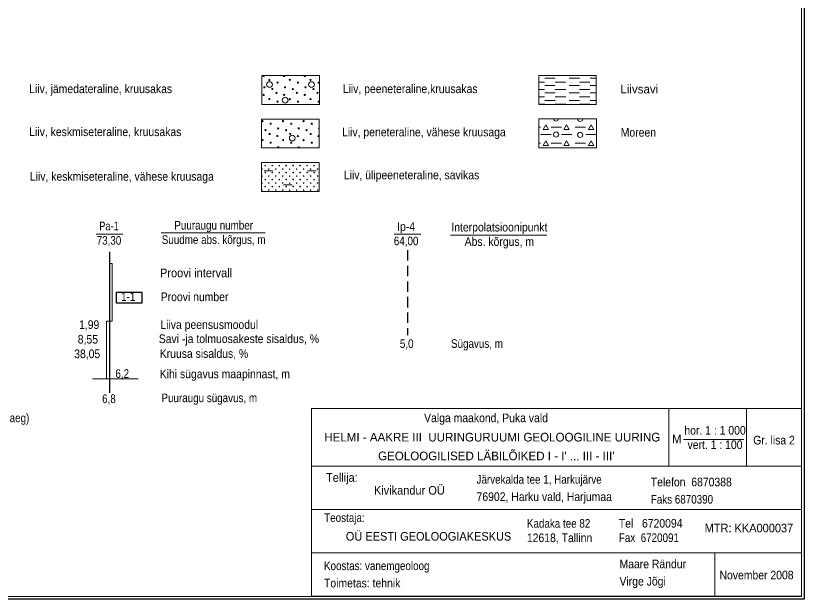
# Model space of a CAD drawing. Extents: x 640104 to 640970, y 6442278 to 6442689.
# Drawn here: x 640696.8 to 640970.3, y 6442282.5 to 6442484.9 of the extents above; entities that cross this region are included whole.
import ezdxf
from ezdxf.enums import TextEntityAlignment as Align

# ---------------------------------------------------------------- set-up
doc = ezdxf.new("R2010")
doc.units = 0
doc.header["$LTSCALE"] = 1.2
doc.linetypes.add('MEDIUM_DASHED', pattern=[4.5, 3, -1.5])
doc.layers.add('50', color=7, linetype='Continuous', lineweight=13)

msp = doc.modelspace()

# ---------------------------------------------------------------- hatches: boundary and pattern name
at = {"layer": '50'}
for points in [[(640784.939, 6442462.605, 1), (640784.519, 6442462.605, 1)], [(640787.767, 6442461.697, 1), (640787.347, 6442461.697, 1)], [(640792.072, 6442462.605, 1), (640791.652, 6442462.605, 1)], [(640794.9, 6442461.697, 1), (640794.48, 6442461.697, 1)], [(640799.205, 6442462.605, 1), (640798.785, 6442462.605, 1)], [(640802.033, 6442461.697, 1), (640801.613, 6442461.697, 1)], [(640783.236, 6442460.072, 1), (640782.816, 6442460.072, 1)], [(640785.983, 6442459.466, 1), (640785.563, 6442459.466, 1)], [(640787.402, 6442458.144, 1), (640786.982, 6442458.144, 1)], [(640790.369, 6442460.072, 1), (640789.949, 6442460.072, 1)], [(640793.116, 6442459.466, 1), (640792.696, 6442459.466, 1)], [(640794.535, 6442458.144, 1), (640794.115, 6442458.144, 1)], [(640797.502, 6442460.072, 1), (640797.082, 6442460.072, 1)], [(640800.249, 6442459.466, 1), (640799.829, 6442459.466, 1)], [(640801.668, 6442458.144, 1), (640801.248, 6442458.144, 1)], [(640782.962, 6442457.428, 1), (640782.542, 6442457.428, 1)], [(640784.939, 6442456.009, 1), (640784.519, 6442456.009, 1)], [(640787.767, 6442455.101, 1), (640787.347, 6442455.101, 1)], [(640790.095, 6442457.428, 1), (640789.675, 6442457.428, 1)], [(640792.072, 6442456.009, 1), (640791.652, 6442456.009, 1)], [(640794.9, 6442455.101, 1), (640794.48, 6442455.101, 1)], [(640797.228, 6442457.428, 1), (640796.808, 6442457.428, 1)], [(640799.205, 6442456.009, 1), (640798.785, 6442456.009, 1)], [(640802.033, 6442455.101, 1), (640801.613, 6442455.101, 1)], [(640782.559, 6442448.354, 1), (640782.139, 6442448.354, 1)], [(640785.386, 6442447.446, 1), (640784.966, 6442447.446, 1)], [(640789.692, 6442448.354, 1), (640789.272, 6442448.354, 1)], [(640792.519, 6442447.446, 1), (640792.099, 6442447.446, 1)], [(640796.825, 6442448.354, 1), (640796.405, 6442448.354, 1)], [(640799.652, 6442447.446, 1), (640799.232, 6442447.446, 1)], [(640783.603, 6442445.215, 1), (640783.183, 6442445.215, 1)], [(640787.989, 6442445.82, 1), (640787.569, 6442445.82, 1)], [(640790.736, 6442445.215, 1), (640790.316, 6442445.215, 1)], [(640795.122, 6442445.82, 1), (640794.702, 6442445.82, 1)], [(640797.869, 6442445.215, 1), (640797.449, 6442445.215, 1)], [(640782.559, 6442441.758, 1), (640782.139, 6442441.758, 1)], [(640785.022, 6442443.893, 1), (640784.602, 6442443.893, 1)], [(640787.714, 6442443.177, 1), (640787.294, 6442443.177, 1)], [(640789.692, 6442441.758, 1), (640789.272, 6442441.758, 1)], [(640792.155, 6442443.893, 1), (640791.735, 6442443.893, 1)], [(640794.847, 6442443.177, 1), (640794.427, 6442443.177, 1)], [(640796.825, 6442441.758, 1), (640796.405, 6442441.758, 1)], [(640799.288, 6442443.893, 1), (640798.868, 6442443.893, 1)], [(640801.98, 6442443.177, 1), (640801.56, 6442443.177, 1)], [(640785.386, 6442440.85, 1), (640784.966, 6442440.85, 1)], [(640792.519, 6442440.85, 1), (640792.099, 6442440.85, 1)], [(640799.652, 6442440.85, 1), (640799.232, 6442440.85, 1)], [(640783.399, 6442432.982, 1), (640783.25, 6442432.833, 1)], [(640783.399, 6442430.563, 1), (640783.25, 6442430.415, 1)], [(640784.608, 6442431.773, 1), (640784.459, 6442431.624, 1)], [(640785.817, 6442432.982, 1), (640785.669, 6442432.833, 1)], [(640785.817, 6442430.563, 1), (640785.669, 6442430.415, 1)], [(640787.026, 6442431.773, 1), (640786.878, 6442431.624, 1)], [(640788.235, 6442432.982, 1), (640788.087, 6442432.833, 1)], [(640788.235, 6442430.563, 1), (640788.087, 6442430.415, 1)], [(640789.445, 6442431.773, 1), (640789.296, 6442431.624, 1)], [(640790.654, 6442432.982, 1), (640790.505, 6442432.833, 1)], [(640790.654, 6442430.563, 1), (640790.505, 6442430.415, 1)], [(640791.863, 6442431.773, 1), (640791.714, 6442431.624, 1)], [(640793.072, 6442432.982, 1), (640792.924, 6442432.833, 1)], [(640793.072, 6442430.563, 1), (640792.924, 6442430.415, 1)], [(640794.281, 6442431.773, 1), (640794.133, 6442431.624, 1)], [(640795.49, 6442432.982, 1), (640795.342, 6442432.833, 1)], [(640795.49, 6442430.563, 1), (640795.342, 6442430.415, 1)], [(640796.699, 6442431.773, 1), (640796.551, 6442431.624, 1)], [(640797.909, 6442432.982, 1), (640797.76, 6442432.833, 1)], [(640797.909, 6442430.563, 1), (640797.76, 6442430.415, 1)], [(640799.118, 6442431.773, 1), (640798.969, 6442431.624, 1)], [(640800.327, 6442432.982, 1), (640800.178, 6442432.833, 1)], [(640800.327, 6442430.563, 1), (640800.178, 6442430.415, 1)], [(640801.536, 6442431.773, 1), (640801.388, 6442431.624, 1)], [(640783.399, 6442428.145, 1), (640783.25, 6442427.997, 1)], [(640784.608, 6442429.354, 1), (640784.459, 6442429.206, 1)], [(640785.817, 6442428.145, 1), (640785.669, 6442427.997, 1)], [(640787.026, 6442429.354, 1), (640786.878, 6442429.206, 1)], [(640788.235, 6442428.145, 1), (640788.087, 6442427.997, 1)], [(640789.445, 6442429.354, 1), (640789.296, 6442429.206, 1)], [(640790.654, 6442428.145, 1), (640790.505, 6442427.997, 1)], [(640791.863, 6442429.354, 1), (640791.714, 6442429.206, 1)], [(640793.072, 6442428.145, 1), (640792.924, 6442427.997, 1)], [(640794.281, 6442429.354, 1), (640794.133, 6442429.206, 1)], [(640795.49, 6442428.145, 1), (640795.342, 6442427.997, 1)], [(640796.699, 6442429.354, 1), (640796.551, 6442429.206, 1)], [(640797.909, 6442428.145, 1), (640797.76, 6442427.997, 1)], [(640799.118, 6442429.354, 1), (640798.969, 6442429.206, 1)], [(640800.327, 6442428.145, 1), (640800.178, 6442427.997, 1)], [(640801.536, 6442429.354, 1), (640801.388, 6442429.206, 1)], [(640783.399, 6442425.727, 1), (640783.25, 6442425.578, 1)], [(640784.608, 6442426.936, 1), (640784.459, 6442426.787, 1)], [(640785.817, 6442425.727, 1), (640785.669, 6442425.578, 1)], [(640787.026, 6442426.936, 1), (640786.878, 6442426.787, 1)], [(640788.235, 6442425.727, 1), (640788.087, 6442425.578, 1)], [(640789.445, 6442426.936, 1), (640789.296, 6442426.787, 1)], [(640790.654, 6442425.727, 1), (640790.505, 6442425.578, 1)], [(640791.863, 6442426.936, 1), (640791.714, 6442426.787, 1)], [(640793.072, 6442425.727, 1), (640792.924, 6442425.578, 1)], [(640794.281, 6442426.936, 1), (640794.133, 6442426.787, 1)], [(640795.49, 6442425.727, 1), (640795.342, 6442425.578, 1)], [(640796.699, 6442426.936, 1), (640796.551, 6442426.787, 1)], [(640797.909, 6442425.727, 1), (640797.76, 6442425.578, 1)], [(640799.118, 6442426.936, 1), (640798.969, 6442426.787, 1)], [(640800.327, 6442425.727, 1), (640800.178, 6442425.578, 1)], [(640801.536, 6442426.936, 1), (640801.388, 6442426.787, 1)], [(640784.608, 6442424.518, 1), (640784.459, 6442424.369, 1)], [(640787.026, 6442424.518, 1), (640786.878, 6442424.369, 1)], [(640789.445, 6442424.518, 1), (640789.296, 6442424.369, 1)], [(640791.863, 6442424.518, 1), (640791.714, 6442424.369, 1)], [(640794.281, 6442424.518, 1), (640794.133, 6442424.369, 1)], [(640796.699, 6442424.518, 1), (640796.551, 6442424.369, 1)], [(640799.118, 6442424.518, 1), (640798.969, 6442424.369, 1)], [(640801.536, 6442424.518, 1), (640801.388, 6442424.369, 1)]]:
    msp.add_hatch(color=256, dxfattribs=at).paths.add_polyline_path(points)

# ---------------------------------------------------------------- linework, layer by layer
for p, q in [((640880.24, 6442461.89), (640878.17, 6442461.89)), ((640883.94, 6442463.25), (640880.34, 6442463.25)), ((640883.94, 6442460.68), (640880.34, 6442460.68)), ((640887.54, 6442461.88), (640883.94, 6442461.88)), ((640892.34, 6442463.25), (640888.74, 6442463.25)), ((640892.34, 6442460.68), (640888.74, 6442460.68)), ((640895.95, 6442461.89), (640892.35, 6442461.89)), ((640898.17, 6442463.25), (640896.05, 6442463.25)), ((640898.17, 6442460.68), (640896.05, 6442460.68)), ((640880.24, 6442459.32), (640878.17, 6442459.32)), ((640883.94, 6442458.11), (640880.34, 6442458.11)), ((640887.54, 6442459.31), (640883.94, 6442459.31)), ((640892.34, 6442458.11), (640888.74, 6442458.11)), ((640895.95, 6442459.32), (640892.35, 6442459.32)), ((640898.17, 6442458.11), (640896.05, 6442458.11)), ((640880.24, 6442456.75), (640878.17, 6442456.75)), ((640883.94, 6442455.54), (640880.34, 6442455.54)), ((640887.54, 6442456.74), (640883.94, 6442456.74)), ((640892.34, 6442455.54), (640888.74, 6442455.54)), ((640895.95, 6442456.75), (640892.35, 6442456.75)), ((640898.17, 6442455.54), (640896.05, 6442455.54)), ((640880.24, 6442454.18), (640878.17, 6442454.18)), ((640887.54, 6442454.17), (640883.94, 6442454.17)), ((640895.95, 6442454.18), (640892.35, 6442454.18)), ((640878.76, 6442446.3), (640878.23, 6442446.3)), ((640886.06, 6442446.29), (640882.46, 6442446.29)), ((640894.46, 6442446.3), (640890.86, 6442446.3)), ((640898.23, 6442446.29), (640898.15, 6442446.29)), ((640882.46, 6442443.74), (640878.86, 6442443.74)), ((640889.66, 6442443.73), (640886.06, 6442443.73)), ((640898.15, 6442443.74), (640894.55, 6442443.74)), ((640878.76, 6442440.74), (640878.23, 6442440.74)), ((640886.06, 6442440.74), (640882.46, 6442440.74)), ((640894.46, 6442440.74), (640890.86, 6442440.74)), ((640898.23, 6442440.74), (640898.15, 6442440.74)), ((640782.89, 6442431.05), (640785.89, 6442431.05)), ((640798.02, 6442431.05), (640801.02, 6442431.05)), ((640789.65, 6442426.19), (640792.65, 6442426.19)), ((640724.64, 6442409.13), (640733.86, 6442409.13)), ((640747.19, 6442409.65), (640783.26, 6442409.65)), ((640828.06, 6442409.13), (640837.28, 6442409.13)), ((640847.59, 6442408.76), (640880.99, 6442408.76)), ((640723.43, 6442359.01), (640739.23, 6442359.01)), ((640923.29, 6442328.63), (640923.29, 6442348.63)), ((640950.3, 6442328.63), (640950.3, 6442348.63)), ((640928.43, 6442337.96), (640949.3, 6442337.96)), ((640799.3, 6442328.63), (640969.3, 6442328.63)), ((640814.82, 6442325.4), (640814.8, 6442325.38)), ((640799.3, 6442313.63), (640969.3, 6442313.63)), ((640799.3, 6442298.63), (640969.3, 6442298.63)), ((640939.3, 6442283.63), (640939.3, 6442298.63))]:
    msp.add_line(p, q, dxfattribs=at)
at = {"layer": '50', "linetype": 'MEDIUM_DASHED', "lineweight": 25}
msp.add_line((640832.65, 6442403.55), (640832.65, 6442374.14), dxfattribs=at)
at = {"layer": '50', "lineweight": 25}
msp.add_line((640729.23, 6442403.02), (640729.23, 6442354.12), dxfattribs=at)
for points in [[(640103.56, 6442688.99), (640970.3, 6442688.99), (640970.3, 6442282.54), (640103.56, 6442282.54)], [(640731.74, 6442389.04), (640740.45, 6442389.04), (640740.45, 6442385.24), (640731.74, 6442385.24)]]:
    msp.add_lwpolyline(points, close=True, dxfattribs=at)
at = {"layer": '50'}
for points in [[(640104.56, 6442687.99), (640969.3, 6442687.99), (640969.3, 6442283.54), (640104.56, 6442283.54)], [(640782.11, 6442464.13), (640802.11, 6442464.13), (640802.11, 6442454.13), (640782.11, 6442454.13)], [(640878.17, 6442464.13), (640898.17, 6442464.13), (640898.17, 6442454.13), (640878.17, 6442454.13)], [(640782.04, 6442449.06), (640802.04, 6442449.06), (640802.04, 6442439.06), (640782.04, 6442439.06)], [(640878.23, 6442449.1), (640898.23, 6442449.1), (640898.23, 6442439.1), (640878.23, 6442439.1)], [(640782.03, 6442433.97), (640802.03, 6442433.97), (640802.03, 6442423.97), (640782.03, 6442423.97)], [(640730.23, 6442379.01), (640730.23, 6442399.01), (640729.23, 6442399.01), (640729.23, 6442379.01)], [(640728.23, 6442379.01), (640728.23, 6442359.01), (640729.23, 6442359.01), (640729.23, 6442379.01)], [(640969.3, 6442348.63), (640799.3, 6442348.63), (640799.3, 6442283.63), (640969.3, 6442283.63)]]:
    msp.add_lwpolyline(points, close=True, dxfattribs=at)
for points in [[(640879.7, 6442445.46), (640879.7, 6442445.49), (640880.65, 6442447.02), (640881.58, 6442445.48), (640879.78, 6442445.49)], [(640886.92, 6442445.46), (640886.92, 6442445.49), (640887.87, 6442447.02), (640888.8, 6442445.48), (640887, 6442445.49)], [(640895.39, 6442445.46), (640895.4, 6442445.49), (640896.34, 6442447.02), (640897.27, 6442445.48), (640895.47, 6442445.49)], [(640879.7, 6442439.91), (640879.7, 6442439.93), (640880.65, 6442441.46), (640881.58, 6442439.92), (640879.78, 6442439.93)], [(640886.92, 6442439.91), (640886.92, 6442439.93), (640887.87, 6442441.46), (640888.8, 6442439.92), (640887, 6442439.93)], [(640895.39, 6442439.91), (640895.4, 6442439.93), (640896.34, 6442441.46), (640897.27, 6442439.92), (640895.47, 6442439.93)]]:
    msp.add_lwpolyline(points, dxfattribs=at)
for centre, radius in [((640784.793, 6442461.022), 1), ((640784.729, 6442462.605), 0.21), ((640787.557, 6442461.697), 0.21), ((640791.862, 6442462.605), 0.21), ((640794.69, 6442461.697), 0.21), ((640799.353, 6442461.022), 1), ((640798.995, 6442462.605), 0.21), ((640801.823, 6442461.697), 0.21), ((640783.026, 6442460.072), 0.21), ((640785.773, 6442459.466), 0.21), ((640787.192, 6442458.144), 0.21), ((640790.159, 6442460.072), 0.21), ((640792.906, 6442459.466), 0.21), ((640794.325, 6442458.144), 0.21), ((640797.292, 6442460.072), 0.21), ((640800.039, 6442459.466), 0.21), ((640801.458, 6442458.144), 0.21), ((640782.752, 6442457.428), 0.21), ((640784.729, 6442456.009), 0.21), ((640787.557, 6442455.101), 0.21), ((640790.217, 6442455.598), 1), ((640789.885, 6442457.428), 0.21), ((640791.862, 6442456.009), 0.21), ((640794.69, 6442455.101), 0.21), ((640797.018, 6442457.428), 0.21), ((640798.995, 6442456.009), 0.21), ((640801.823, 6442455.101), 0.21), ((640782.349, 6442448.354), 0.21), ((640785.176, 6442447.446), 0.21), ((640789.482, 6442448.354), 0.21), ((640792.309, 6442447.446), 0.21), ((640796.615, 6442448.354), 0.21), ((640799.442, 6442447.446), 0.21), ((640783.393, 6442445.215), 0.21), ((640787.779, 6442445.82), 0.21), ((640790.526, 6442445.215), 0.21), ((640794.912, 6442445.82), 0.21), ((640797.659, 6442445.215), 0.21), ((640884.207, 6442443.687), 0.9), ((640892.589, 6442443.564), 0.9), ((640782.349, 6442441.758), 0.21), ((640784.812, 6442443.893), 0.21), ((640787.504, 6442443.177), 0.21), ((640789.482, 6442441.758), 0.21), ((640792.691, 6442442.465), 1), ((640791.945, 6442443.893), 0.21), ((640794.637, 6442443.177), 0.21), ((640796.615, 6442441.758), 0.21), ((640799.078, 6442443.893), 0.21), ((640801.77, 6442443.177), 0.21), ((640785.176, 6442440.85), 0.21), ((640792.309, 6442440.85), 0.21), ((640799.442, 6442440.85), 0.21), ((640783.325, 6442432.907), 0.105), ((640783.325, 6442430.489), 0.105), ((640784.534, 6442431.698), 0.105), ((640785.743, 6442432.907), 0.105), ((640785.743, 6442430.489), 0.105), ((640786.952, 6442431.698), 0.105), ((640788.161, 6442432.907), 0.105), ((640788.161, 6442430.489), 0.105), ((640789.37, 6442431.698), 0.105), ((640790.579, 6442432.907), 0.105), ((640790.579, 6442430.489), 0.105), ((640791.789, 6442431.698), 0.105), ((640792.998, 6442432.907), 0.105), ((640792.998, 6442430.489), 0.105), ((640794.207, 6442431.698), 0.105), ((640795.416, 6442432.907), 0.105), ((640795.416, 6442430.489), 0.105), ((640796.625, 6442431.698), 0.105), ((640797.834, 6442432.907), 0.105), ((640797.834, 6442430.489), 0.105), ((640799.044, 6442431.698), 0.105), ((640800.253, 6442432.907), 0.105), ((640800.253, 6442430.489), 0.105), ((640801.462, 6442431.698), 0.105), ((640783.325, 6442428.071), 0.105), ((640784.534, 6442429.28), 0.105), ((640785.743, 6442428.071), 0.105), ((640786.952, 6442429.28), 0.105), ((640788.161, 6442428.071), 0.105), ((640789.37, 6442429.28), 0.105), ((640790.579, 6442428.071), 0.105), ((640791.789, 6442429.28), 0.105), ((640792.998, 6442428.071), 0.105), ((640794.207, 6442429.28), 0.105), ((640795.416, 6442428.071), 0.105), ((640796.625, 6442429.28), 0.105), ((640797.834, 6442428.071), 0.105), ((640799.044, 6442429.28), 0.105), ((640800.253, 6442428.071), 0.105), ((640801.462, 6442429.28), 0.105), ((640783.325, 6442425.653), 0.105), ((640784.534, 6442426.862), 0.105), ((640785.743, 6442425.653), 0.105), ((640786.952, 6442426.862), 0.105), ((640788.161, 6442425.653), 0.105), ((640789.37, 6442426.862), 0.105), ((640790.579, 6442425.653), 0.105), ((640791.789, 6442426.862), 0.105), ((640792.998, 6442425.653), 0.105), ((640794.207, 6442426.862), 0.105), ((640795.416, 6442425.653), 0.105), ((640796.625, 6442426.862), 0.105), ((640797.834, 6442425.653), 0.105), ((640799.044, 6442426.862), 0.105), ((640800.253, 6442425.653), 0.105), ((640801.462, 6442426.862), 0.105), ((640784.534, 6442424.443), 0.105), ((640786.952, 6442424.443), 0.105), ((640789.37, 6442424.443), 0.105), ((640791.789, 6442424.443), 0.105), ((640794.207, 6442424.443), 0.105), ((640796.625, 6442424.443), 0.105), ((640799.044, 6442424.443), 0.105), ((640801.462, 6442424.443), 0.105)]:
    msp.add_circle(centre, radius, dxfattribs=at)
for centre, radius, start, end in [((640782.752, 6442464.024), 0.21, 150.74597, 29.25403), ((640789.885, 6442464.024), 0.21, 150.74597, 29.25403), ((640797.018, 6442464.024), 0.21, 150.74597, 29.25403), ((640884.207, 6442449.241), 0.9, 188.96929, 351.03071), ((640892.589, 6442449.119), 0.9, 181.15583, 358.84417), ((640802.045, 6442445.82), 0.21, 91.76464, 268.23536), ((640787.779, 6442439.224), 0.21, 306.48162, 233.51838), ((640794.912, 6442439.224), 0.21, 306.48162, 233.51838), ((640802.045, 6442439.224), 0.21, 91.76464, 233.51838), ((640782.115, 6442431.698), 0.105, 212.33453, 147.66547), ((640782.115, 6442429.28), 0.105, 212.33453, 147.66547), ((640782.115, 6442426.862), 0.105, 212.33453, 147.66547), ((640782.115, 6442424.443), 0.105, 212.33453, 147.66547)]:
    msp.add_arc(centre, radius, start, end, dxfattribs=at)

# ---------------------------------------------------------------- texts
for s, width, p in [('Liiv, jämedateraline, kruusakas', 0.9, (640726.205, 6442458.05)), ('Liiv, peeneteraline,kruusakas', 0.9, (640833.59, 6442458.06)), ('Liiv, keskmiseteraline, kruusakas', 0.9, (640727.835, 6442443.15)), ('Liiv, peneteraline, vähese kruusaga', 0.9, (640838.35, 6442443.06)), ('Moreen', 0.9, (640912.765, 6442442.96)), ('Liiv, keskmiseteraline, vähese kruusaga', 0.9, (640733.56, 6442427.67)), ('Liiv, ülipeeneteraline, savikas', 0.9, (640834.07, 6442428.17)), ('Pa-1', 0.8, (640729.1, 6442410.48)), ('Puuraugu number', 0.85, (640765.42, 6442410.74)), ('Ip-4', 0.9, (640832.185, 6442410.29)), ('Interpolatsioonipunkt', 0.9, (640864.535, 6442410.07)), ('Suudme abs. kõrgus, m', 0.85, (640765.415, 6442405.74)), ('73,30', 0.85, (640729.095, 6442405.48)), ('64,00', 0.85, (640832.18, 6442405.29)), ('Abs. kõrgus, m', 0.9, (640864.53, 6442405.07)), ('Proovi intervall', 0.95, (640759.305, 6442394.21)), ('1-1', 0.85, (640735.775, 6442385.97)), ('Proovi number', 0.9, (640758.79, 6442385.91)), ('1,99', 0.9, (640722.23, 6442376.27)), ('Liiva peensusmoodul', 0.9, (640763.89, 6442376.28)), ('8,55', 0.9, (640721.785, 6442371.2)), ('Savi -ja tolmuosakeste sisaldus, %', 0.9, (640774.17, 6442371.37)), ('5,0', 0.85, (640832.385, 6442369.67)), ('Sügavus, m', 0.85, (640856.765, 6442369.7)), ('38,05', 0.9, (640721.55, 6442366.15)), ('Kruusa sisaldus, %', 0.9, (640762.06, 6442366.24)), ('6,2', 0.85, (640733.695, 6442359.29)), ('Kihi sügavus maapinnast, m', 0.9, (640769.29, 6442359.18)), ('6,8', 0.85, (640729.085, 6442350.55)), ('Puuraugu sügavus, m', 0.85, (640763.89, 6442350.88)), ('Veetaseme abs. kõrgus, m (mõõtmise aeg)', 0.85, (640668.87, 6442343.92)), ('Valga maakond, Puka vald', 0.9, (640859.9, 6442343.94)), ('hor. 1 : 1 000', 0.9, (640939.36, 6442339.62)), ('vert. 1 : 100', 0.9, (640939.36, 6442334.62)), ('Gr. lisa 2', 0.9, (640959.82, 6442336.21)), ('     Kivikandur OÜ', 0.95, (640830.66, 6442318.82)), ('November 2008', 0.9, (640953.755, 6442289.42))]:
    msp.add_text(s, height=3, dxfattribs=dict(at, width=width)).set_placement(p, align=Align.CENTER)
for s, p in [('Liivsavi', (640913.08, 6442457.95)), ('HELMI - AAKRE III  UURINGURUUMI GEOLOOGILINE UURING', (640862.07, 6442337.24)), ('M', (640926.115, 6442336.63)), ("GEOLOOGILISED LÄBILÕIKED I - I' ... III - III'", (640863.47, 6442330.74))]:
    msp.add_text(s, height=3, dxfattribs=at).set_placement(p, align=Align.CENTER)
for s, width, p in [('Tellija:', 0.95, (640804.39, 6442323.26)), ('Järvekalda tee 1, Harkujärve', 0.85, (640856.62, 6442322.61)), ('Telefon  6870388', 0.9, (640917.07, 6442321.69)), ('76902, Harku vald, Harjumaa', 0.9, (640856.62, 6442316.61)), ('Faks 6870390', 0.85, (640917.07, 6442315.69)), ('Teostaja:', 0.85, (640803.76, 6442309.32)), ('Kadaka tee 82', 0.85, (640874.09, 6442307.34)), ('Tel   6720094', 0.9, (640905.98, 6442307.38)), ('MTR: KKA000037', 0.95, (640935.76, 6442305.73)), ('OÜ EESTI GEOLOOGIAKESKUS', 0.95, (640811.27, 6442302.86)), ('12618, Tallinn', 0.9, (640874.09, 6442302.34)), ('Fax  6720091', 0.85, (640905.98, 6442302.38)), ('Koostas: vanemgeoloog', 0.85, (640803.7, 6442292.64)), ('Maare Rändur', 0.9, (640906.22, 6442293.28)), ('Toimetas: tehnik', 0.9, (640803.7, 6442286.64)), ('Virge Jõgi', 0.9, (640906.22, 6442287.28))]:
    msp.add_text(s, height=3, dxfattribs=dict(at, width=width)).set_placement(p)

doc.saveas('drawing.dxf')
